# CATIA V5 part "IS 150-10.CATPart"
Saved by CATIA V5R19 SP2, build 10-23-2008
Part number: IS 150-10
Bounding box of the stored display mesh (mm): x -15.868 to 15.868, y -15.868 to 15.868, z 0 to 70
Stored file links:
  C:\Users\Bora\Desktop\3D Katı model\IS serisi\IS 150\IS 150-10.CATPart
  C:\Program Files\Dassault Systemes\B19\intel_a\reffiles\standard\MetricThickPitch.txt
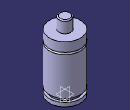
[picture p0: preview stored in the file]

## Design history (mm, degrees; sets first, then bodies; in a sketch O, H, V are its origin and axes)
Body1 (main body)
  Sketch1 on yz-plane, origin (0, 0, 0), H (0, 1, 0), V (0, 0, 1)
    point P3 (6, 69)
    point P5 (6, 69)
    point P7 (16, 48.5)
    point P8 (16, 46.5)
    point P12 (16, 46.5)
    point P13 (16, 48.5)
    line L1 (16, 0) -> (16, 4)
    line L2 (6, 69) -> (6, 58)
    arc A1 centre (5, 69) radius 1 from (6, 69) to (5, 70) ccw
    arc A2 centre (16, 47.5) radius 1 from (16, 48.5) to (16, 46.5) ccw
    line L3 (13.5, 7.5) -> (13.5, 4)
    line L4 (16, 7.5) -> (16, 46.5)
    line L5 (16, 48.5) -> (16, 58)
    line L6 (5, 70) -> (0, 70)
    point P15 (0, 70)
    line L7 (6, 58) -> (16, 58)
    line L8 (13.5, 7.5) -> (16, 7.5)
    line L9 (13.5, 4) -> (16, 4)
    line L10 (16, 0) -> (0, 0)
    tangency: L6 A1
    coincidence: P15 V, P3 P5, P7 P13, P8 P12
    horizontal: L7 H, L8 H, L9 H, L10 H
  Shaft1: profile Sketch1, axis Sketch1.V, angle 360
  Sketch2 on face of Shaft1 from Sketch1.L10, origin (0, 0, 0), H (1, 0, 0), V (0, -1, 0)
    point P1 (0, 0)
    distance P1 V = 0
  Hole1: placed by Sketch2, at (0, 0, 0) direction (0, 0, 1), diameter 6.647, depth 7, threaded "M8", thread diameter 8, thread depth 7, pitch 1.25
